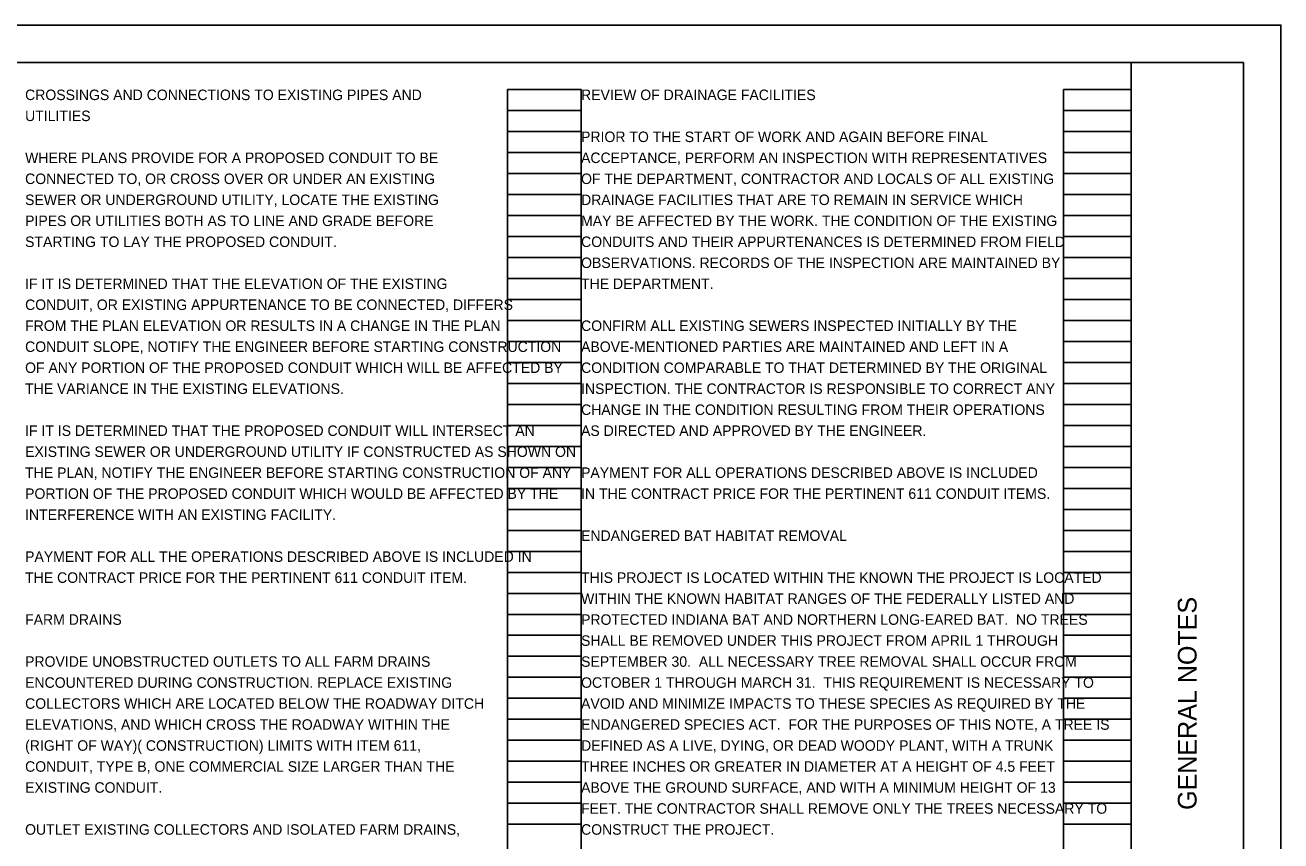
# Model space of a CAD drawing. Extents: x 0 to 36.9, y 0 to 22.
# Drawn here: x 17.24 to 34, y 11.12 to 22 of the extents above; entities that cross this region are included whole.
import ezdxf

# ---------------------------------------------------------------- set-up
doc = ezdxf.new("R2010")
doc.units = 0
for name, color, linetype in [('SH_Border', 7, 'Continuous'), ('SH_Cut_Line', 7, 'Continuous'), ('SH_Data', 7, 'Continuous'), ('SH_Text', 7, 'Continuous')]:
    doc.layers.add(name, color=color, linetype=linetype)

msp = doc.modelspace()

# ---------------------------------------------------------------- linework, layer by layer
at = {"layer": 'SH_Border'}
msp.add_line((32, 0.5), (32, 21.5), dxfattribs=at)
msp.add_lwpolyline([(1.5, 21.5), (33.5, 21.5), (33.5, 0.5), (1.5, 0.5)], close=True, dxfattribs=at)
at = {"layer": 'SH_Cut_Line'}
msp.add_lwpolyline([(0, 0), (34, 0), (34, 22), (0, 22)], close=True, dxfattribs=at)
at = {"layer": 'SH_Data'}
for p, q in [((23.68, 0.98), (23.68, 21.14)), ((23.68, 21.14), (24.66, 21.14)), ((24.66, 0.98), (24.66, 21.14)), ((31.1, 0.98), (31.1, 21.14)), ((31.1, 21.14), (32, 21.14)), ((32, 0.98), (32, 21.14)), ((23.68, 20.86), (24.66, 20.86)), ((31.1, 20.86), (32, 20.86)), ((23.68, 20.58), (24.66, 20.58)), ((31.1, 20.58), (32, 20.58)), ((23.68, 20.3), (24.66, 20.3)), ((31.1, 20.3), (32, 20.3)), ((23.68, 20.02), (24.66, 20.02)), ((31.1, 20.02), (32, 20.02)), ((23.68, 19.74), (24.66, 19.74)), ((31.1, 19.74), (32, 19.74)), ((23.68, 19.46), (24.66, 19.46)), ((31.1, 19.46), (32, 19.46)), ((23.68, 19.18), (24.66, 19.18)), ((31.1, 19.18), (32, 19.18)), ((23.68, 18.9), (24.66, 18.9)), ((31.1, 18.9), (32, 18.9)), ((23.68, 18.62), (24.66, 18.62)), ((31.1, 18.62), (32, 18.62)), ((23.68, 18.34), (24.66, 18.34)), ((31.1, 18.34), (32, 18.34)), ((23.68, 18.06), (24.66, 18.06)), ((31.1, 18.06), (32, 18.06)), ((23.68, 17.78), (24.66, 17.78)), ((31.1, 17.78), (32, 17.78)), ((23.68, 17.5), (24.66, 17.5)), ((31.1, 17.5), (32, 17.5)), ((23.68, 17.22), (24.66, 17.22)), ((31.1, 17.22), (32, 17.22)), ((23.68, 16.94), (24.66, 16.94)), ((31.1, 16.94), (32, 16.94)), ((23.68, 16.66), (24.66, 16.66)), ((31.1, 16.66), (32, 16.66)), ((23.68, 16.38), (24.66, 16.38)), ((31.1, 16.38), (32, 16.38)), ((23.68, 16.1), (24.66, 16.1)), ((31.1, 16.1), (32, 16.1)), ((23.68, 15.82), (24.66, 15.82)), ((31.1, 15.82), (32, 15.82)), ((23.68, 15.54), (24.66, 15.54)), ((31.1, 15.54), (32, 15.54)), ((23.68, 15.26), (24.66, 15.26)), ((31.1, 15.26), (32, 15.26)), ((23.68, 14.98), (24.66, 14.98)), ((31.1, 14.98), (32, 14.98)), ((23.68, 14.7), (24.66, 14.7)), ((31.1, 14.7), (32, 14.7)), ((23.68, 14.42), (24.66, 14.42)), ((31.1, 14.42), (32, 14.42)), ((23.68, 14.14), (24.66, 14.14)), ((31.1, 14.14), (32, 14.14)), ((23.68, 13.86), (24.66, 13.86)), ((31.1, 13.86), (32, 13.86)), ((23.68, 13.58), (24.66, 13.58)), ((31.1, 13.58), (32, 13.58)), ((23.68, 13.3), (24.66, 13.3)), ((31.1, 13.3), (32, 13.3)), ((23.68, 13.02), (24.66, 13.02)), ((31.1, 13.02), (32, 13.02)), ((23.68, 12.74), (24.66, 12.74)), ((31.1, 12.74), (32, 12.74)), ((23.68, 12.46), (24.66, 12.46)), ((31.1, 12.46), (32, 12.46)), ((23.68, 12.18), (24.66, 12.18)), ((31.1, 12.18), (32, 12.18)), ((23.68, 11.9), (24.66, 11.9)), ((31.1, 11.9), (32, 11.9)), ((23.68, 11.62), (24.66, 11.62)), ((31.1, 11.62), (32, 11.62)), ((23.68, 11.34), (24.66, 11.34)), ((31.1, 11.34), (32, 11.34))]:
    msp.add_line(p, q, dxfattribs=at)

# ---------------------------------------------------------------- texts
msp.add_text('GENERAL NOTES', height=0.25, rotation=90, dxfattribs=at).set_placement((32.875, 11.531))
at = {"layer": 'SH_Text'}
for s, p in [('CROSSINGS AND CONNECTIONS TO EXISTING PIPES AND', (17.24, 21)), ('REVIEW OF DRAINAGE FACILITIES', (24.66, 21)), ('UTILITIES', (17.24, 20.72)), ('PRIOR TO THE START OF WORK AND AGAIN BEFORE FINAL', (24.66, 20.44)), ('WHERE PLANS PROVIDE FOR A PROPOSED CONDUIT TO BE', (17.24, 20.16)), ('ACCEPTANCE, PERFORM AN INSPECTION WITH REPRESENTATIVES', (24.66, 20.16)), ('CONNECTED TO, OR CROSS OVER OR UNDER AN EXISTING', (17.24, 19.88)), ('OF THE DEPARTMENT, CONTRACTOR AND LOCALS OF ALL EXISTING', (24.66, 19.88)), ('SEWER OR UNDERGROUND UTILITY, LOCATE THE EXISTING', (17.24, 19.6)), ('DRAINAGE FACILITIES THAT ARE TO REMAIN IN SERVICE WHICH', (24.66, 19.6)), ('PIPES OR UTILITIES BOTH AS TO LINE AND GRADE BEFORE', (17.24, 19.32)), ('MAY BE AFFECTED BY THE WORK. THE CONDITION OF THE EXISTING', (24.66, 19.32)), ('STARTING TO LAY THE PROPOSED CONDUIT.', (17.24, 19.04)), ('CONDUITS AND THEIR APPURTENANCES IS DETERMINED FROM FIELD', (24.66, 19.04)), ('OBSERVATIONS. RECORDS OF THE INSPECTION ARE MAINTAINED BY', (24.66, 18.76)), ('IF IT IS DETERMINED THAT THE ELEVATION OF THE EXISTING', (17.24, 18.48)), ('THE DEPARTMENT.', (24.66, 18.48)), ('CONDUIT, OR EXISTING APPURTENANCE TO BE CONNECTED, DIFFERS', (17.24, 18.2)), ('FROM THE PLAN ELEVATION OR RESULTS IN A CHANGE IN THE PLAN', (17.24, 17.92)), ('CONFIRM ALL EXISTING SEWERS INSPECTED INITIALLY BY THE', (24.66, 17.92)), ('CONDUIT SLOPE, NOTIFY THE ENGINEER BEFORE STARTING CONSTRUCTION', (17.24, 17.64)), ('ABOVE-MENTIONED PARTIES ARE MAINTAINED AND LEFT IN A', (24.66, 17.64)), ('OF ANY PORTION OF THE PROPOSED CONDUIT WHICH WILL BE AFFECTED BY', (17.24, 17.36)), ('CONDITION COMPARABLE TO THAT DETERMINED BY THE ORIGINAL', (24.66, 17.36)), ('THE VARIANCE IN THE EXISTING ELEVATIONS.', (17.24, 17.08)), ('INSPECTION. THE CONTRACTOR IS RESPONSIBLE TO CORRECT ANY', (24.66, 17.08)), ('CHANGE IN THE CONDITION RESULTING FROM THEIR OPERATIONS', (24.66, 16.8)), ('IF IT IS DETERMINED THAT THE PROPOSED CONDUIT WILL INTERSECT AN', (17.24, 16.52)), ('AS DIRECTED AND APPROVED BY THE ENGINEER.', (24.66, 16.52)), ('EXISTING SEWER OR UNDERGROUND UTILITY IF CONSTRUCTED AS SHOWN ON', (17.24, 16.24)), ('THE PLAN, NOTIFY THE ENGINEER BEFORE STARTING CONSTRUCTION OF ANY', (17.24, 15.96)), ('PAYMENT FOR ALL OPERATIONS DESCRIBED ABOVE IS INCLUDED', (24.66, 15.96)), ('PORTION OF THE PROPOSED CONDUIT WHICH WOULD BE AFFECTED BY THE', (17.24, 15.68)), ('IN THE CONTRACT PRICE FOR THE PERTINENT 611 CONDUIT ITEMS.', (24.66, 15.68)), ('INTERFERENCE WITH AN EXISTING FACILITY.', (17.24, 15.4)), ('ENDANGERED BAT HABITAT REMOVAL', (24.66, 15.12)), ('PAYMENT FOR ALL THE OPERATIONS DESCRIBED ABOVE IS INCLUDED IN', (17.24, 14.84)), ('THE CONTRACT PRICE FOR THE PERTINENT 611 CONDUIT ITEM.', (17.24, 14.56)), ('THIS PROJECT IS LOCATED WITHIN THE KNOWN THE PROJECT IS LOCATED ', (24.66, 14.56)), ('WITHIN THE KNOWN HABITAT RANGES OF THE FEDERALLY LISTED AND ', (24.66, 14.28)), ('FARM DRAINS', (17.24, 14)), ('PROTECTED INDIANA BAT AND NORTHERN LONG-EARED BAT.  NO TREES ', (24.66, 14)), ('SHALL BE REMOVED UNDER THIS PROJECT FROM APRIL 1 THROUGH ', (24.66, 13.72)), ('PROVIDE UNOBSTRUCTED OUTLETS TO ALL FARM DRAINS', (17.24, 13.44)), ('SEPTEMBER 30.  ALL NECESSARY TREE REMOVAL SHALL OCCUR FROM ', (24.66, 13.44)), ('ENCOUNTERED DURING CONSTRUCTION. REPLACE EXISTING', (17.24, 13.16)), ('OCTOBER 1 THROUGH MARCH 31.  THIS REQUIREMENT IS NECESSARY TO ', (24.66, 13.16)), ('COLLECTORS WHICH ARE LOCATED BELOW THE ROADWAY DITCH', (17.24, 12.88)), ('AVOID AND MINIMIZE IMPACTS TO THESE SPECIES AS REQUIRED BY THE ', (24.66, 12.88)), ('ELEVATIONS, AND WHICH CROSS THE ROADWAY WITHIN THE', (17.24, 12.6)), ('ENDANGERED SPECIES ACT.  FOR THE PURPOSES OF THIS NOTE, A TREE IS ', (24.66, 12.6)), ('(RIGHT OF WAY)( CONSTRUCTION) LIMITS WITH ITEM 611,', (17.24, 12.32)), ('DEFINED AS A LIVE, DYING, OR DEAD WOODY PLANT, WITH A TRUNK ', (24.66, 12.32)), ('CONDUIT, TYPE B, ONE COMMERCIAL SIZE LARGER THAN THE', (17.24, 12.04)), ('THREE INCHES OR GREATER IN DIAMETER AT A HEIGHT OF 4.5 FEET ', (24.66, 12.04)), ('EXISTING CONDUIT.', (17.24, 11.76)), ('ABOVE THE GROUND SURFACE, AND WITH A MINIMUM HEIGHT OF 13 ', (24.66, 11.76)), ('FEET. THE CONTRACTOR SHALL REMOVE ONLY THE TREES NECESSARY TO ', (24.66, 11.48)), ('OUTLET EXISTING COLLECTORS AND ISOLATED FARM DRAINS,', (17.24, 11.2)), ('CONSTRUCT THE PROJECT.', (24.66, 11.2))]:
    msp.add_text(s, height=0.14, dxfattribs=at).set_placement(p)

doc.saveas('drawing.dxf')
